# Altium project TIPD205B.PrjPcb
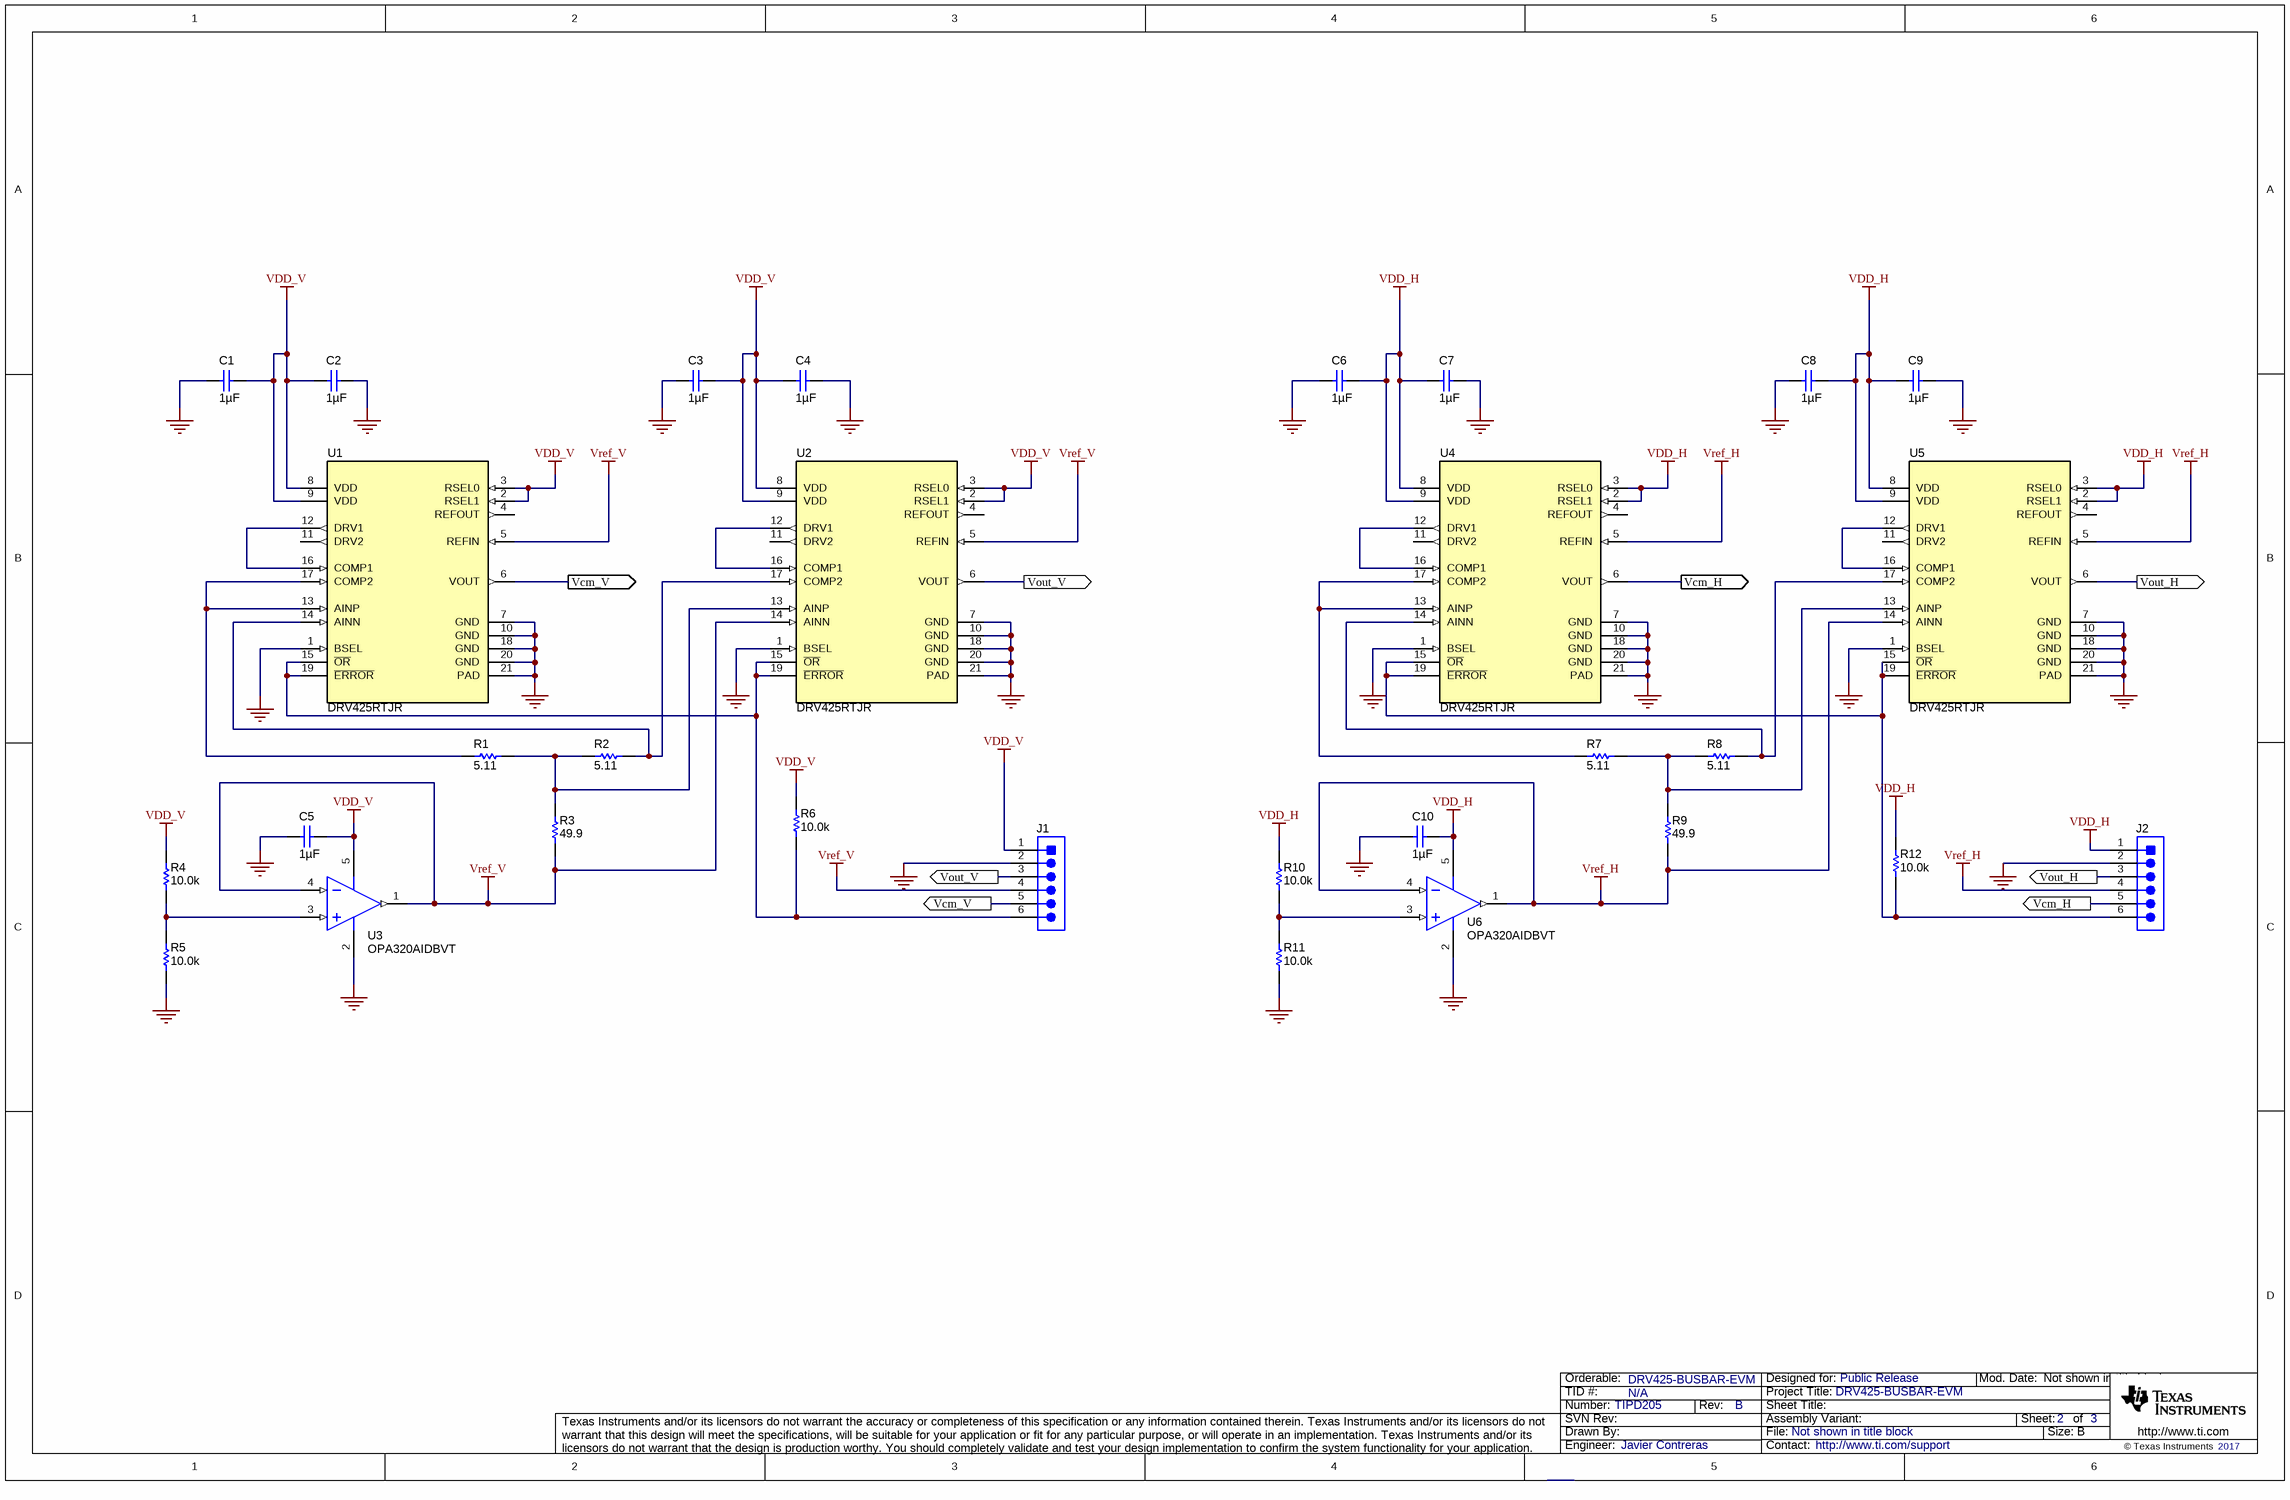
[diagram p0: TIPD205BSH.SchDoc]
CopyrightYear: 2017; EVM_Orderable: DRV425-BUSBAR-EVM; PCB_Layout: Javier Contreras; PCB_Rev: B; PRJ_Customer: Public Release; PRJ_Engineer: Javier Contreras; PRJ_Number: TIPD205; PRJ_Title: DRV425-BUSBAR-EVM; SCH_Rev: B; TechSupport: http://www.ti.com/support; TID: N/A
2 sheets, 50 parts. Net scope: flat (ports and power ports of the same name join across sheets).
Board file: TIPD205B.PcbDoc
Sheets:
  TIPD205BSH.SchDoc
  TIPD205BHW.SchDoc

## Sheet TIPD205BSH.SchDoc
size 431 x 279 mm; Date: Not shown in title block; ApprovedBy: Not shown in title block; CheckedBy: Not shown in title block; Author: Not shown in title block; CompanyName: Not shown in title block; Engineer: Not shown in title block; Organization: Not shown in title block; Address1: Not shown in title block; Address2: Not shown in title block; Address3: Not shown in title block; Address4: Not shown in title block; DocumentNumber: 1; Revision: Use project parameter SCH_Rev; SheetNumber: 2; SheetTotal: 3; PageSetup: Record=PageOptions¦CenterHorizontal=True¦CenterVertical=True¦PrintScale=1.00¦XCorrection=1.00¦YCorrection=1.00¦PrintKind=0¦BorderSize=5000000¦LeftOffset=0¦BottomOffset=0¦Orientation=2¦PaperLength=1000¦PaperWidth=1000¦Scale=100¦PaperSource=15¦PrintQuality=600¦MediaType=1¦DitherType=10¦PaperKind=Letter¦PrintScaleMode=1

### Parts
C1  ValueDisplayed: 1µF  [0603]  (hidden comment: C0603C105K3RACTU)
C2  ValueDisplayed: 1µF  [0603]  (hidden comment: C0603C105K3RACTU)
C3  ValueDisplayed: 1µF  [0603]  (hidden comment: C0603C105K3RACTU)
C4  ValueDisplayed: 1µF  [0603]  (hidden comment: C0603C105K3RACTU)
C5  ValueDisplayed: 1µF  [0603]  (hidden comment: C0603C105K3RACTU)
C6  ValueDisplayed: 1µF  [0603]  (hidden comment: C0603C105K3RACTU)
C7  ValueDisplayed: 1µF  [0603]  (hidden comment: C0603C105K3RACTU)
C8  ValueDisplayed: 1µF  [0603]  (hidden comment: C0603C105K3RACTU)
C9  ValueDisplayed: 1µF  [0603]  (hidden comment: C0603C105K3RACTU)
C10  ValueDisplayed: 1µF  [0603]  (hidden comment: C0603C105K3RACTU)
J1  292207-6  [TE_292207-6]  (value not drawn)
J2  292207-6  [TE_292207-6]  (value not drawn)
R1  ValueDisplayed: 5.11  [0805_HV]  (hidden comment: RC0805FR-075R11L)
R2  ValueDisplayed: 5.11  [0805_HV]  (hidden comment: RC0805FR-075R11L)
R3  ValueDisplayed: 49.9  [0805_HV]  (hidden comment: RT0805BRD0749R9L)
R4  ValueDisplayed: 10.0k  [0402]  (hidden comment: CRCW040210K0FKED)
R5  ValueDisplayed: 10.0k  [0402]  (hidden comment: CRCW040210K0FKED)
R6  ValueDisplayed: 10.0k  [0402]  (hidden comment: CRCW040210K0FKED)
R7  ValueDisplayed: 5.11  [0805_HV]  (hidden comment: RC0805FR-075R11L)
R8  ValueDisplayed: 5.11  [0805_HV]  (hidden comment: RC0805FR-075R11L)
R9  ValueDisplayed: 49.9  [0805_HV]  (hidden comment: RT0805BRD0749R9L)
R10  ValueDisplayed: 10.0k  [0402]  (hidden comment: CRCW040210K0FKED)
R11  ValueDisplayed: 10.0k  [0402]  (hidden comment: CRCW040210K0FKED)
R12  ValueDisplayed: 10.0k  [0402]  (hidden comment: CRCW040210K0FKED)
U1  DRV425RTJR  [RTJ20_no_vias]
U2  DRV425RTJR  [RTJ20_no_vias]
U3  OPA320AIDBVT  [DBV0005A_N]
U4  DRV425RTJR  [RTJ20_no_vias]
U5  DRV425RTJR  [RTJ20_no_vias]
U6  OPA320AIDBVT  [DBV0005A_N]

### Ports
Vcm_H (out), Vcm_V (out), Vout_H (out), Vout_V (out)

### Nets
GND_H: C6.2 C7.1 C8.2 C9.1 C10.2 J2.2 R11.1 U4.1(BSEL) U4.7(GND) U4.10(GND) U4.18(GND) U4.20(GND) U4.21(PAD) U5.1(BSEL) U5.7(GND) U5.10(GND) U5.18(GND) U5.20(GND) U5.21(PAD) U6.2(V-)
GND_V: C1.2 C2.1 C3.2 C4.1 C5.2 J1.2 R5.1 U1.1(BSEL) U1.7(GND) U1.10(GND) U1.18(GND) U1.20(GND) U1.21(PAD) U2.1(BSEL) U2.7(GND) U2.10(GND) U2.18(GND) U2.20(GND) U2.21(PAD) U3.2(V-)
VDD_H: C6.1 C7.2 C8.1 C9.2 C10.1 J2.1 R10.2 R12.2 U4.2(RSEL1) U4.3(RSEL0) U4.8(VDD) U4.9(VDD) U5.2(RSEL1) U5.3(RSEL0) U5.8(VDD) U5.9(VDD) U6.5(V+)
VDD_V: C1.1 C2.2 C3.1 C4.2 C5.1 J1.1 R4.2 R6.2 U1.2(RSEL1) U1.3(RSEL0) U1.8(VDD) U1.9(VDD) U2.2(RSEL1) U2.3(RSEL0) U2.8(VDD) U2.9(VDD) U3.5(V+)
Vref_H: J2.4 R9.1 U4.5(REFIN) U5.5(REFIN) U5.14(AINN) U6.1(OUT) U6.4(IN-)
Vref_V: J1.4 R3.1 U1.5(REFIN) U2.5(REFIN) U2.14(AINN) U3.1(OUT) U3.4(IN-)
Vcm_H: J2.5 U4.6(VOUT) ; port Vcm_H
Vcm_V: J1.5 U1.6(VOUT) ; port Vcm_V
Vout_H: J2.3 U5.6(VOUT) ; port Vout_H
Vout_V: J1.3 U2.6(VOUT) ; port Vout_V
NetJ1_6: J1.6 R6.1 U1.15(~{OR}) U1.19(~{ERROR}) U2.15(~{OR}) U2.19(~{ERROR})
NetJ2_6: J2.6 R12.1 U4.15(~{OR}) U4.19(~{ERROR}) U5.15(~{OR}) U5.19(~{ERROR})
NetR1_1: R1.1 R2.2 R3.2 U2.13(AINP)
NetR1_2: R1.2 U1.13(AINP) U1.17(COMP2)
NetR2_1: R2.1 U1.14(AINN) U2.17(COMP2)
NetR4_1: R4.1 R5.2 U3.3(IN+)
NetR7_1: R7.1 R8.2 R9.2 U5.13(AINP)
NetR7_2: R7.2 U4.13(AINP) U4.17(COMP2)
NetR8_1: R8.1 U4.14(AINN) U5.17(COMP2)
NetR10_1: R10.1 R11.2 U6.3(IN+)
NetU1_12: U1.12(DRV1) U1.16(COMP1)
NetU2_12: U2.12(DRV1) U2.16(COMP1)
NetU4_12: U4.12(DRV1) U4.16(COMP1)
NetU5_12: U5.12(DRV1) U5.16(COMP1)

Not connected (* = marked no-connect by the designer): U1 4(REFOUT) 11(DRV2); U2 4(REFOUT) 11(DRV2); U4 4(REFOUT) 11(DRV2); U5 4(REFOUT) 11(DRV2)

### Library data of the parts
C1-C10 = C0603C105K3RACTU: CAP, CERM, 1 µF, 25 V, +/- 10%, X7R, 0603; Manufacturer: Kemet; Polarized: N; CompType: Capacitor; Value: 1uF; U/M: EA; Cap_F: 0.000001; Tolerance_%: 10; Value1: Unknown; VDC_V: 25; Value2: 25V; TaMin_C: -55; TaMax_C: 125; SizeArea_mm2: 1.28; SizeAreaWB_mm2: 4.68; SizeX_mm: 1.6; SizeY_mm: 0.8; SizeZ_mm: 1; AEC Category: Q200
J1 J2 = 292207-6: Header(shrouded), 1.5mm, 6x1, Tin, TH; Manufacturer: TE Connectivity; SymbolCreator: a0412235; Pitch_mm: 1.5; Gender: Male; Shrouded: Y; Row_Count: 1; Current_A: 2; Voltage_V: 50
R1 R2 R7 R8 = RC0805FR-075R11L: RES, 5.11, 1%, 0.125 W, 0805; Manufacturer: Yageo America; CompType: Resistor; Value: 5.11; U/M: EA; Value_Code: 5R11; Tolerance_%: 1; Power_W: 0.125; Value2: 0.125W; VDC_V: 150; TempCo: 200 ppm/C; SizeArea_mm2: 2.5; SizeX_mm: 2; SizeY_mm: 1.25; SizeZ_mm: 1.45; EIA_Code: E96; AEC Category: Q200
R3 R9 = RT0805BRD0749R9L: RES, 49.9, 0.1%, 0.125 W, 0805; Manufacturer: Yageo America; CompType: Resistor; Value: 49.9; U/M: EA; Value_Code: 49R9; Tolerance_%: 0.1; Power_W: 0.125; Value2: 0.125W; VDC_V: 150; TempCo: 25 ppm/C; SizeArea_mm2: 2.5; SizeX_mm: 2; SizeY_mm: 1.25; SizeZ_mm: 1.45; EIA_Code: E192; AEC Category: Q200
R4-R6 R10-R12 = CRCW040210K0FKED: RES, 10.0 k, 1%, 0.063 W, 0402; Manufacturer: Vishay-Dale; CompType: Resistor; Value: 10.0k; U/M: EA; Res_ohm: 10000; Value_Code: 10k0; Tolerance_%: 1; Power_W: 0.063; Value2: 0.063W; VDC_V: 50; TempCo: 100 ppm/C; SizeArea_mm2: 0.5; SizeZ_mm: 0.6; EIA_Code: E96; AEC Category: Q200
U1 U2 U4 U5 = DRV425RTJR: Fully Integrated Precision Fluxgate Magnetic Field Sensor and readout, RTJ0020G (WQFN-20); Alternate PartNumber: DRV425RTJT; Manufacturer: Texas Instruments; SymbolCreator: Altium; CompType: IC; U/M: EA; SizeArea_mm2: 16; SizeAreaWB_mm2: 25; SizeX_mm: 4; SizeZ_mm: 0.8
U3 U6 = OPA320AIDBVT: Precision, 20 MHz, 0.9 pA Ib, RRIO, CMOS Operational Amplifier, 1.8 to 5.5 V, -40 to 125 degC, 5-pin SOT23 (DBV0005A), Green (RoHS & no Sb/Br); Manufacturer: Texas Instruments; Alternate PartNumber: Equivalent; CMRR(Min)(dB): 100; IIB(Max)(pA): 0.9; Iq per channel(Max)(mA): 1.75; Number of Channels: 2; Offset Drift(Typ)(uV/C): 1.5; Slew Rate(Typ)(V/us): 10; Sub Family: High Output Current Amplifier (>=50mA), Low Input Bias Current Amp (<=10pA), Low Noise Amp (<=10nV/rtHz), Low Offset Voltage Amplifier (<=500uV), Low Supply Voltage Amplifier (<=2.7V), Precision Amplifier; Total Supply Voltage(Max)(+5V is 5, +/-5V is 10): 5.5; Total Supply Voltage(Min)(+5V is 5, +/-5V is 10): 1.8; Vio (25C)(Max)(mV): 0.15; Vn at 1kHz(Typ)(nV/rtHz): 8.5

## Sheet TIPD205BHW.SchDoc
size 431 x 279 mm; Date: Not shown in title block; ApprovedBy: Not shown in title block; CheckedBy: Not shown in title block; Author: Not shown in title block; CompanyName: Not shown in title block; Engineer: Not shown in title block; Organization: Not shown in title block; Address1: Not shown in title block; Address2: Not shown in title block; Address3: Not shown in title block; Address4: Not shown in title block; DocumentNumber: 1; Revision: Use project parameter SCH_Rev; SheetNumber: 3; SheetTotal: 3; PageSetup: Record=PageOptions¦CenterHorizontal=True¦CenterVertical=True¦PrintScale=1.00¦XCorrection=1.00¦YCorrection=1.00¦PrintKind=0¦BorderSize=5000000¦LeftOffset=0¦BottomOffset=0¦Orientation=2¦PaperLength=1000¦PaperWidth=1000¦Scale=100¦PaperSource=15¦PrintQuality=600¦MediaType=1¦DitherType=10¦PaperKind=Letter¦PrintScaleMode=1
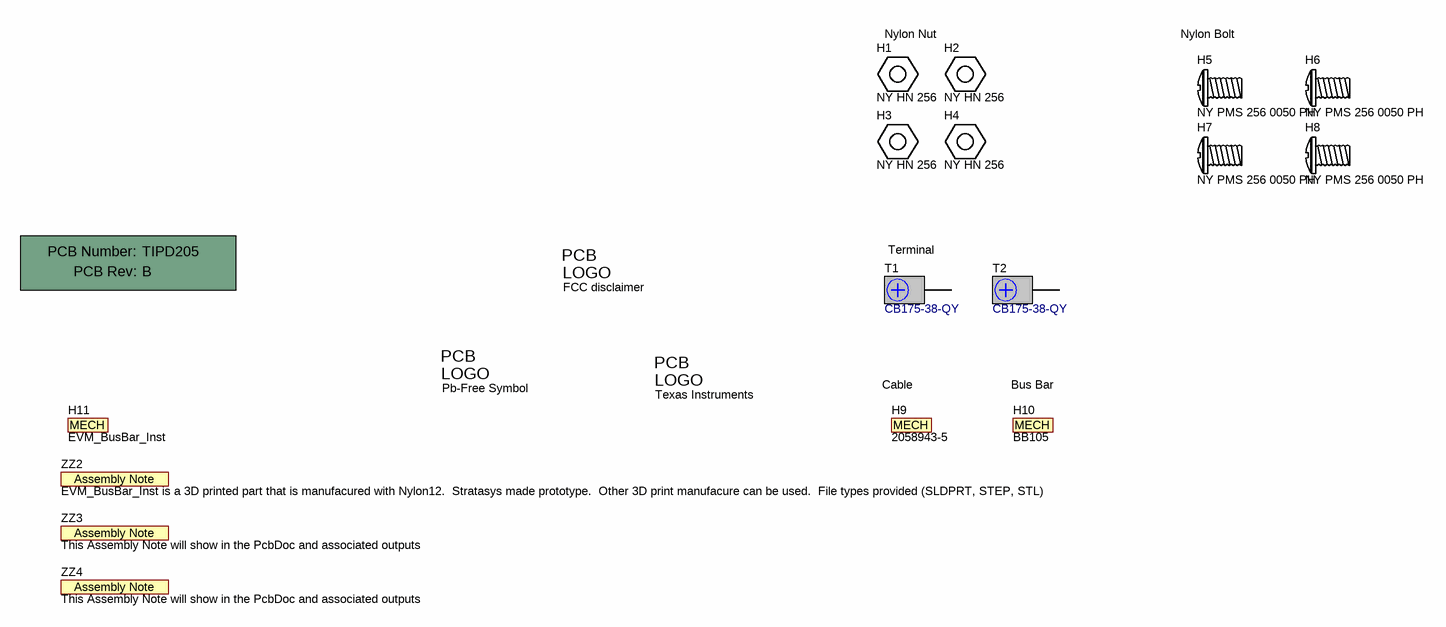
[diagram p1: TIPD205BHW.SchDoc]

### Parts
!PCB  Printed Circuit Board  (value not drawn)  (mechanical)
H1  NY HN 256  (mechanical)
H2  NY HN 256  (mechanical)
H3  NY HN 256  (mechanical)
H4  NY HN 256  (mechanical)
H5  NY PMS 256 0050 PH  (mechanical)
H6  NY PMS 256 0050 PH  (mechanical)
H7  NY PMS 256 0050 PH  (mechanical)
H8  NY PMS 256 0050 PH  (mechanical)
H9  2058943-5  (mechanical)
H10  BB105  (mechanical)
H11  EVM_BusBar_Inst  (mechanical)
Logo1  Pb-Free Symbol  [Pb-Free_Overlay_Small]  (no BOM)
Logo2  Texas Instruments  [TI_Symbol_Overlay_Small]  (no BOM)
Logo3  FCC disclaimer  [FCC_disclaimer]  (no BOM)
T1  CB175-38-QY  [Panduit_CB175-38-QY]
T2  CB175-38-QY  [Panduit_CB175-38-QY]
ZZ2  EVM_BusBar_Inst is a 3D printed part that is manufacured with Nylon12.  Stratasys made prototype.  Other 3D print manufacure can be used.  File types provided (SLDPRT, STEP, STL)  [AssemblyNote]  (no BOM)
ZZ3  This Assembly Note will show in the PcbDoc and associated outputs  [AssemblyNote]  (no BOM)
ZZ4  This Assembly Note will show in the PcbDoc and associated outputs  [AssemblyNote]  (no BOM)

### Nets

Not connected (* = marked no-connect by the designer): T1 1; T2 1

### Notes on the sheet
- Nylon Nut
- (near H5) Nylon Bolt
- (near T1) Terminal
- (near H9) Cable
- (near H10) Bus Bar

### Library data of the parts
!PCB = PCB: Manufacturer: Any; PartNumber: TIPD205; SymbolCreator: a0412235
H1-H4 = NY HN 256: Nylon Nut, 2-56, 3/16"; Manufacturer: B&F Fastener Supply; SymbolCreator: a0412235
H5-H8 = NY PMS 256 0050 PH: Screw, Pan Philips, Nylon, 2-56; Manufacturer: B&F Fastener Supply; SymbolCreator: a0412235
H9 = MechPart: Cable assembly; Manufacturer: TE Connectivity AMP Connectors; SymbolCreator: codlsc; CompType: Mechanical; U/M: EA
H10 = MechPart: Bus bar 0.4" hole, standoffs, nuts, washers; Manufacturer: Storm Power Components; SymbolCreator: codlsc; CompType: Mechanical; U/M: EA
H11 = MechPart: EVM_BusBar_Inst  3D printed part with Nylon 12.  See Note ZZ2; SymbolCreator: codlsc; CompType: Mechanical; U/M: EA
Logo1 = Pb-Free: SymbolCreator: a0412235
Logo2 = TI_Logo: Texas Instrument Corporate Signature; SymbolCreator: a0412235
Logo3 = FCC_disclaimer: SymbolCreator: a0412235
T1 T2 = CB175-38-QY: Lug, Rectangular, 3/0-4 AWG, 3/8 Stud, with screw; Manufacturer: Panduit; SymbolCreator: crossc
ZZ2-ZZ4 = AssemblyNote: SymbolCreator: codlsc

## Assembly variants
001: all parts fitted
